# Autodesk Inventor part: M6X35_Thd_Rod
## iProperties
Shininess: 64.0
Length Units: 11269
Angle Units: 11279
Time Units: 11290
Mass Units: 11283
Length Display Precision: 3
Angle Display Precision: 2
Compacted: True
Part Number: M6X35_Thd_Rod
Document SubType Name: Modeling
Created: 2004-08
Material: Stainless Steel, Austenitic
Designer: John Blackburn
Manufacturer: Standard
Standards Organization: Custom
Density: 0.0
Volumn: 0.0
Area: 0.0
PropertySet Name: Model Information
Control State: 0
Master: False
Checked Out: False
Author: John Blackburn
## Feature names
1. Extrusion1
2. Chamfer1
